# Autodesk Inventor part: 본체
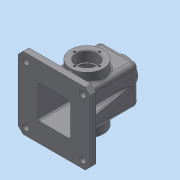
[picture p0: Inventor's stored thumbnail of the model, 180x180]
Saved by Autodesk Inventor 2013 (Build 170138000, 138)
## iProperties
Created: 2018-10
Part Number: 본체
Material: 일반
Document SubType Name: Modeling
Designer: Administrator
Density: 1 g/cm^3
Author: Administrator
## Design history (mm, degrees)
sketch "스케치1"
  geometry: L1 (-32.5, -32.5)-(32.5, -32.5); L2 (32.5, -32.5)-(32.5, 32.5); L3 (32.5, 32.5)-(-32.5, 32.5); L4 (-32.5, 32.5)-(-32.5, -32.5); L5 (-32.5, -32.5)-(32.5, 32.5); L6 (32.5, -32.5)-(-32.5, 32.5); 1 further point
  constraints: 12 end point, 2 midpoint, 2 parallel, 1 horizontal, 1 perpendicular
  dimensions: "d0" = 65 distance of L3.end L2.end; "d1" = 65 distance of L2.end L1.end
extrude "돌출1" new body sketch "스케치1" stored distance "d2" = 110; taper "d3" = 0 deg
fillet "모깎기1" dims "d4" = 8
feature "쉘1" dims "d5" = 5
node "작업 평면1"
sketch "스케치3"
  geometry: C1 r 27.5 at (24.5, 55); 1 further point
  constraints: 1 centre point, 1 coincident
  dimensions: "d10" = 55 diameter of C1
extrude "돌출3" join sketch "스케치3" stored distance "d11" = 15; taper "d12" = 0 deg
sketch "스케치4"
  geometry: C1 r 27.5 at (0, 0) reference; C2 r 17.5 at (0, 0)
  constraints: 1 centre point, 1 coincident
  dimensions: "d13" = 35 diameter of C2
extrude "돌출4" cut sketch "스케치4" distance "d14" = 17; taper "d15" = 0 deg
sketch "스케치5"
  geometry: C1 r 17.5 at (0, 0) reference; C2 r 15 at (0, 0)
  constraints: 1 centre point, 1 coincident
  dimensions: "d16" = 30 diameter of C2
extrude "돌출5" cut sketch "스케치5" distance "d17" = 3; taper "d18" = 0 deg
sketch "스케치6"
  geometry: C1 r 17.5 at (0, 0) reference; 1 further point
  constraints: 1 vertical alignment
  dimensions: "d19" = 21 distance of C1.centre point (0, 21)
hole "구멍1" sketch "스케치6" at (0, 21) diameter "d20" = 3.242; stored, may be unused: countersink angle "d24" = 90 deg, drill point angle "d26" = 118 deg; dims "d21" = 8, "d22" = 4, "d23" = 2, "d25" = 10
node "작업 평면2"
sketch "스케치7"
  geometry: C1 r 20 at (0, 0); 1 further point
  constraints: 1 centre point, 1 coincident
  dimensions: "d31" = 40 diameter of C1
extrude "돌출6" join sketch "스케치7" stored distance "d32" = 3; taper "d33" = 7 deg
hole "구멍2" diameter "d36" = 22.835; stored, may be unused: countersink angle "d40" = 90 deg, drill point angle "d42" = 0 deg; dims "d34" = 10, "d35" = 10, "d37" = 8, "d38" = 4, "d39" = 2, "d41" = 10
sketch "스케치8"
  geometry: L1 (-24.5, -32.5)-(24.5, -32.5) reference; L2 (32.5, -24.5)-(32.5, 24.5) reference; L3 (24.5, 32.5)-(-24.5, 32.5) reference; L4 (-32.5, 24.5)-(-32.5, -24.5) reference; L5 (-60, -60)-(60, -60); L6 (60, -60)-(60, 60); L7 (60, 60)-(-60, 60); L8 (-60, 60)-(-60, -60); L9 (-60, -60)-(60, 60); L10 (60, -60)-(-60, 60); A1 r 8 centre (24.5, -24.5) between (24.5, -32.5) and (32.5, -24.5) reference; A2 r 8 centre (24.5, 24.5) between (32.5, 24.5) and (24.5, 32.5) reference; A3 r 8 centre (-24.5, 24.5) between (-24.5, 32.5) and (-32.5, 24.5) reference; A4 r 8 centre (-24.5, -24.5) between (-32.5, -24.5) and (-24.5, -32.5) reference; 1 further point
  constraints: 12 end point, 2 midpoint, 2 parallel, 1 horizontal, 1 perpendicular
  dimensions: "d43" = 120 distance of L7.end L6.end; "d44" = 120 distance of L6.end L5.end
extrude "돌출7" join sketch "스케치8" distance "d45" = 10; taper "d46" = 0 deg
chamfer "모따기1" distance "d47" = 8; stored, may be unused: second distance "d48" = 2, angle "d49" = 45 deg
sketch "스케치9"
  geometry: L1 (20, 65)-(21.228, 55) reference; L2 (21.228, 55)-(24.5, 55) reference; L3 (32.5, 47)-(32.5, -45) reference; L4 (32.5, -45)-(60, -45) reference; L5 (60, -45)-(60, -55) reference; L6 (60, -55)-(27.5, -55) reference; L7 (27.5, -55)-(27.5, 47) reference; L8 (24.5, 50)-(11.418, 50) reference; L9 (11.418, 50)-(11.418, 65) reference; L10 (11.418, 65)-(20, 65) reference; L11 (-24.5, 55)-(-21.228, 55) reference; L12 (-21.228, 55)-(-20, 65) reference; L13 (-20, 65)-(-11.418, 65) reference; L14 (-11.418, 65)-(-11.418, 50) reference; L15 (-11.418, 50)-(-24.5, 50) reference; L16 (-27.5, 47)-(-27.5, -55) reference; L17 (-27.5, -55)-(-60, -55) reference; L18 (-60, -55)-(-60, -45) reference; L19 (-60, -45)-(-32.5, -45) reference; L20 (-32.5, -45)-(-32.5, 47) reference; L21 (-48, -45)-(-42.191, -12.053); A1 r 8 centre (24.5, 47) between (32.5, 47) and (24.5, 55) reference; A2 r 3 centre (24.5, 47) between (27.5, 47) and (24.5, 50) reference; A3 r 8 centre (-24.5, 47) between (-24.5, 55) and (-32.5, 47) reference; A4 r 3 centre (-24.5, 47) between (-24.5, 50) and (-27.5, 47) reference; 1 further point
  constraints: 2 end point, 1 point on line
  dimensions: "d50" = 10 deg angle of L21 L18; "d51" = 12 distance from line of L21.start L18
feature "리브1" sketch "스케치9" dims "d52" = 1, "d53" = 10, "d54" = 0, "d55" = 0, "d56" = 1, "d57" = 1
sketch "스케치10"
  geometry: L1 (-17.5, -30.5)-(-17.5, -47.5) reference; L2 (-17.5, -47.5)-(-19.379, -47.5) reference; L3 (-19.379, -47.5)-(-19.379, -37.5) reference; L4 (-19.379, -37.5)-(-21, -36.526) reference; L5 (-21, -36.526)-(-22.621, -37.5) reference; L6 (-22.621, -37.5)-(-22.621, -47.5) reference; L7 (-22.621, -47.5)-(-27.5, -47.5) reference; L8 (-27.5, -47.5)-(-27.5, -32.5) reference; L9 (-27.5, -32.5)-(-45, -32.5) reference; L10 (-45, -32.5)-(-45, -60) reference; L11 (-45, -60)-(-55, -60) reference; L12 (-55, -60)-(-55, -27.5) reference; L13 (-55, -27.5)-(-15, -27.5) reference; L14 (-15, -27.5)-(-15, -30.5) reference; L15 (-15, -30.5)-(-17.5, -30.5) reference; L16 (27.5, -32.5)-(27.5, -47.5) reference; L17 (27.5, -47.5)-(22.621, -47.5) reference; L18 (22.621, -47.5)-(22.621, -37.5) reference; L19 (22.621, -37.5)-(21, -36.526) reference; L20 (21, -36.526)-(19.379, -37.5) reference; L21 (19.379, -37.5)-(19.379, -47.5) reference; L22 (19.379, -47.5)-(17.5, -47.5) reference; L23 (17.5, -47.5)-(17.5, -30.5) reference; L24 (17.5, -30.5)-(15, -30.5) reference; L25 (15, -30.5)-(15, -27.5) reference; L26 (15, -27.5)-(47, -27.5) reference; L27 (50, -24.5)-(50, -11.418) reference; L28 (50, -11.418)-(65, -11.418) reference; L29 (65, -11.418)-(65, -20) reference; L30 (65, -20)-(55, -21.228) reference; L31 (55, -21.228)-(55, -24.5) reference; L32 (47, -32.5)-(27.5, -32.5) reference; L33 (27.5, 47.5)-(27.5, 32.5) reference; L34 (27.5, 32.5)-(47, 32.5) reference; L35 (55, 24.5)-(55, 21.228) reference; L36 (55, 21.228)-(65, 20) reference; L37 (65, 20)-(65, 11.418) reference; L38 (65, 11.418)-(50, 11.418) reference; L39 (50, 11.418)-(50, 24.5) reference; L40 (47, 27.5)-(15, 27.5) reference; L41 (15, 27.5)-(15, 30.5) reference; L42 (15, 30.5)-(17.5, 30.5) reference; L43 (17.5, 30.5)-(17.5, 47.5) reference; L44 (17.5, 47.5)-(19.379, 47.5) reference; L45 (19.379, 47.5)-(19.379, 37.5) reference; L46 (19.379, 37.5)-(21, 36.526) reference; L47 (21, 36.526)-(22.621, 37.5) reference; L48 (22.621, 37.5)-(22.621, 47.5) reference; L49 (22.621, 47.5)-(27.5, 47.5) reference; L50 (-27.5, 32.5)-(-27.5, 47.5) reference; L51 (-27.5, 47.5)-(-22.621, 47.5) reference; L52 (-22.621, 47.5)-(-22.621, 37.5) reference; L53 (-22.621, 37.5)-(-21, 36.526) reference; L54 (-21, 36.526)-(-19.379, 37.5) reference; L55 (-19.379, 37.5)-(-19.379, 47.5) reference; L56 (-19.379, 47.5)-(-17.5, 47.5) reference; L57 (-17.5, 47.5)-(-17.5, 30.5) reference; L58 (-17.5, 30.5)-(-15, 30.5) reference; L59 (-15, 30.5)-(-15, 27.5) reference; L60 (-15, 27.5)-(-55, 27.5) reference; L61 (-55, 27.5)-(-55, 60) reference; L62 (-55, 60)-(-45, 60) reference; L63 (-45, 60)-(-45, 32.5) reference; L64 (-45, 32.5)-(-27.5, 32.5) reference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; A1 r 3 centre (47, -24.5) between (47, -27.5) and (50, -24.5) reference; A2 r 8 centre (47, -24.5) between (47, -32.5) and (55, -24.5) reference; A3 r 8 centre (47, 24.5) between (55, 24.5) and (47, 32.5) reference; A4 r 3 centre (47, 24.5) between (50, 24.5) and (47, 27.5) reference; 1 further point
  constraints: 2 end point, 1 parallel, 1 point on line
  dimensions: "d58" = 15 distance between parallel lines of L65 L60
feature "리브2" sketch "스케치10" dims "d59" = 1, "d60" = 6, "d61" = 0, "d62" = 0, "d63" = 1, "d64" = 1
sketch "스케치11"
  geometry: C1 r 5 at (-47.5, 47.5); C2 r 5 at (47.5, 47.5); C3 r 5 at (-47.5, -47.5); C4 r 5 at (47.5, -47.5); 1 further point
  constraints: 4 centre point, 2 horizontal alignment, 2 vertical alignment
  dimensions: "d65" = 10 diameter of C1; "d66" = 10 diameter of C2; "d67" = 95 distance of C2.centre C1.centre; "d68" = 10 diameter of C3; "d69" = 10 diameter of C4; "d70" = 95 distance of C4.centre C2.centre; "d71" = 47.5 horizontal distance of C4.centre point (0, 0); "d72" = 47.5 horizontal distance of C2.centre point (0, 0)
extrude "돌출8" cut sketch "스케치11" stored distance "d73" = 10; taper "d74" = 0 deg
sketch "스케치12"
  geometry: L1 (4.5, 18)-(44.5, 18) reference; L2 (-8, 0)-(-8, -92) reference; 1 further point
  constraints: 1 other
  dimensions: "d75" = 26 distance from line of point (24.5, -8) L1; "d76" = 32.5 distance from line of point (24.5, -8) L2
feature "엠보싱1" sketch "스케치12" dims "d0" = 65, "d1" = 65, "d77" = 0.5, "d78" = 0
fillet "모깎기2" dims "d79" = 0.3
chamfer "모따기2" distance "d80" = 1; stored, may be unused: second distance "d81" = 2, angle "d82" = 45 deg
fillet "모깎기4" dims "d84" = 3
fillet "모깎기5" dims "d85" = 3
fillet "모깎기6" dims "d86" = 1
fillet "모깎기7" dims "d87" = 3
fillet "모깎기8" dims "d88" = 3
node "솔리드1"
mirror "대칭1"
pattern_circular "원형 패턴1" dims angle "d28" = 360 deg
mirror "대칭2"
mirror "대칭3"
mirror "대칭4"
node "절단 모서리 투영1"
node "절단 모서리 투영2"
other parameters: "d9" = 15
